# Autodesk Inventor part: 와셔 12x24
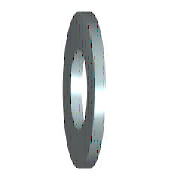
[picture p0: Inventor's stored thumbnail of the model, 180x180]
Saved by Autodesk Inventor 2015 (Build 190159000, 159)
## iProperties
IsCustomPart: 1
Created: 2012-02
Part Number: 와셔 12x24
Material: 스테인리스강
Description: 평면 와셔
Document SubType Name: Modeling
Standard: KS B 1326
Designer: mduedu
Standards Organization: KS
Language: ko-KR
Size Designation: 12x24
Categories: <MemberInstance><Categories><Category DisplayName="조임쇠" InternalName="e4da775c-781d-43d5-af7c-5136215cf5a6" Mnemonic="FSTN"><Category DisplayName="와셔" InternalN
Density: 1 g/cm^3
Appearance: 파란색 - 벽 페인트 - 광택
Author: mduedu
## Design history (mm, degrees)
sketch "스케치"
  geometry: C1 r 12 at (0, 0); C2 r 6.5 at (0, 0); 1 further point
  constraints: 2 centre point, 2 coincident
  dimensions: "d0" = 13 diameter of C2 (= SD1); "d1" = 24 diameter of C1 (= SD2)
extrude "본체" new body sketch "스케치" distance "d2" = 2.5 (= SD); taper "d3" = 0 deg
workaxis "Work Axis1"
workplane "Work Plane1"
body "Solid1"
other parameters: "SD1" = 13 [user parameter; used in 1 equation term], "SD2" = 24 [user parameter; used in 1 equation term], "SD" = 2.5 [user parameter; used in 1 equation term], "d4" = 0, "d5" = 0, "d6" = 0, "d7" = 0, "NND" = 12 [user parameter]
